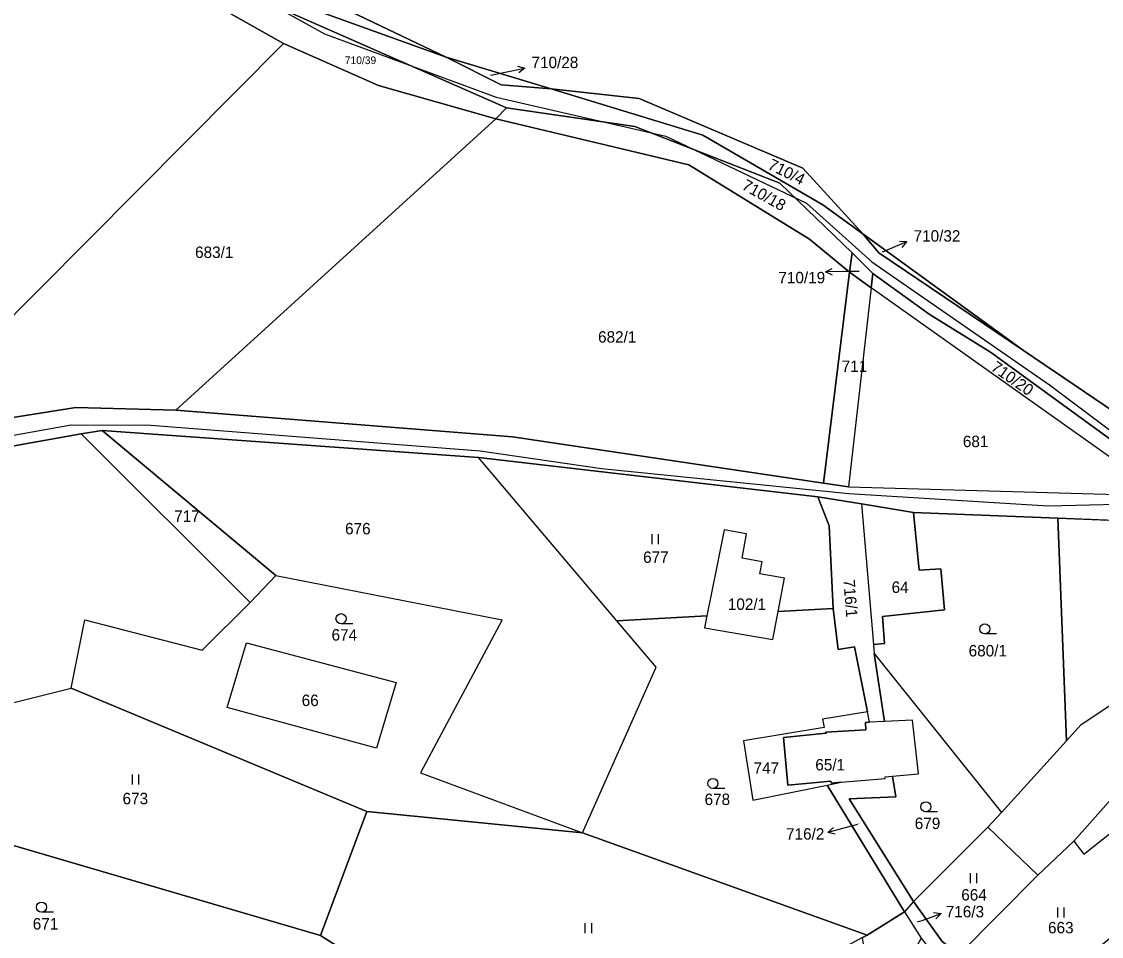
# Model space of a CAD drawing. Extents: x -590606 to -587796, y -1065936 to -1062515.
# Drawn here: x -589718.9 to -589558.4, y -1064672.2 to -1064536.2 of the extents above; entities that cross this region are included whole.
import ezdxf

# ---------------------------------------------------------------- set-up
doc = ezdxf.new("R2010")
doc.units = 0
for name, color, linetype in [('Cesty', 7, 'Continuous'), ('Parcela nároku', 7, 'Continuous'), ('Parcelní číslo', 7, 'Continuous'), ('Vnější obvod_ Studené', 7, 'Continuous'), ('Vrstva 30', 7, 'Continuous'), ('Územní plán', 7, 'Continuous')]:
    doc.layers.add(name, color=color, linetype=linetype)

msp = doc.modelspace()

# ---------------------------------------------------------------- linework, layer by layer
at = {"layer": 'Cesty'}
for points in [[(-589892.17, -1064369.93), (-589875.26, -1064390.63), (-589869.59, -1064400.17), (-589860.61, -1064415.28), (-589855.62, -1064428.91), (-589851.76, -1064436.47), (-589835.09, -1064454.08), (-589818.14, -1064470.08), (-589809.98, -1064474.85), (-589789.91, -1064479.31), (-589769.84, -1064483.14), (-589746.37, -1064490.42), (-589728.15, -1064501.15), (-589708.7, -1064515.97), (-589695.75, -1064525.84), (-589673.94, -1064537.99), (-589648.4, -1064547.43), (-589623.17, -1064553.21), (-589602.26, -1064563.18), (-589592.55, -1064571.88), (-589566.17, -1064590.19), (-589543.56, -1064607.17)], [(-589312.39, -1064575.92), (-589318.72, -1064584.83), (-589335.76, -1064596.6), (-589354.95, -1064613.9), (-589370.21, -1064620.11), (-589392.14, -1064624.65), (-589405.6, -1064625.31), (-589467.35, -1064625.2), (-589485.5, -1064624.04), (-589517.23, -1064616.87), (-589543.56, -1064607.17), (-589549.94, -1064607.84), (-589566.34, -1064608.24), (-589595.98, -1064606.38), (-589632.73, -1064602.69), (-589650.77, -1064600.08), (-589699.72, -1064596.26), (-589711.59, -1064596.2), (-589764.62, -1064605.69), (-589799.36, -1064611.91)]]:
    msp.add_lwpolyline(points, dxfattribs=at)
at = {"layer": 'Parcela nároku'}
for points in [[(-589805.3, -1064473.64), (-589768.97, -1064479.77), (-589741.12, -1064488.48), (-589688.24, -1064525.96), (-589655.82, -1064541.47), (-589681.45, -1064532.18), (-589702.19, -1064520.36), (-589727.96, -1064499.92), (-589745.58, -1064489.29), (-589769.07, -1064481.35), (-589801.78, -1064475.28)], [(-589724.71, -1064505.14), (-589693.05, -1064528.65), (-589646.88, -1064549.01), (-589648.45, -1064550.62), (-589665.91, -1064545.7), (-589680.03, -1064539.44), (-589706.11, -1064524.65), (-589725.8, -1064508.32)], [(-589725.8, -1064508.32), (-589706.11, -1064524.65), (-589680.03, -1064539.44), (-589738.08, -1064597.9), (-589752.19, -1064600.19), (-589746.83, -1064575.48), (-589738.54, -1064544.17)], [(-589680.03, -1064539.44), (-589738.08, -1064597.9), (-589710.88, -1064593.56), (-589696.02, -1064593.97), (-589648.45, -1064550.62), (-589665.91, -1064545.7)], [(-589655.82, -1064541.47), (-589640.22, -1064546.2), (-589647.67, -1064545.57)], [(-589602.81, -1064558), (-589593.92, -1064567.75), (-589599.87, -1064563.44), (-589617.67, -1064553.05), (-589640.22, -1064546.2), (-589627.14, -1064547.63)], [(-589627.8, -1064551.78), (-589606.26, -1064560.21), (-589595.48, -1064570.57), (-589595.88, -1064573.42), (-589601.81, -1064568.51), (-589619.77, -1064557.49), (-589648.45, -1064550.62), (-589646.88, -1064549.01)], [(-589619.77, -1064557.49), (-589648.45, -1064550.62), (-589696.02, -1064593.97), (-589645.99, -1064597.91), (-589599.74, -1064604.8), (-589595.88, -1064573.42), (-589601.81, -1064568.51)], [(-589593.92, -1064567.75), (-589570.02, -1064585.07), (-589591.52, -1064570.55)], [(-589595.48, -1064570.57), (-589592.41, -1064573.65), (-589592.68, -1064575.78), (-589595.88, -1064573.42)], [(-589599.74, -1064604.8), (-589595.88, -1064573.42), (-589592.68, -1064575.78), (-589596.03, -1064605.35)], [(-589592.41, -1064573.65), (-589584.07, -1064579.7), (-589574.93, -1064585.33), (-589545.68, -1064606.61), (-589549.09, -1064606.72), (-589592.68, -1064575.78)], [(-589592.68, -1064575.78), (-589596.03, -1064605.35), (-589549.09, -1064606.72)], [(-589755.28, -1064641.85), (-589755.52, -1064646.24), (-589711.55, -1064635.28), (-589709.54, -1064625.13), (-589692.09, -1064629.64), (-589684.98, -1064622.56), (-589710.09, -1064597.48), (-589753, -1064605.14)], [(-589681.13, -1064618.54), (-589706.94, -1064597.01), (-589710.09, -1064597.48), (-589684.98, -1064622.56)], [(-589630.46, -1064625.3), (-589651.05, -1064601), (-589706.94, -1064597.01), (-589681.13, -1064618.54), (-589647.53, -1064625.14), (-589659.66, -1064647.91), (-589635.57, -1064656.82), (-589624.62, -1064632.2)], [(-589651.05, -1064601), (-589600.62, -1064606.83), (-589598.89, -1064611.14), (-589598.31, -1064623.43), (-589606.49, -1064623.91), (-589605.57, -1064618.96), (-589609.22, -1064618.29), (-589608.89, -1064616.51), (-589611.85, -1064615.97), (-589611.19, -1064612.37), (-589614.53, -1064611.74), (-589615.62, -1064617.2), (-589617.08, -1064624.52), (-589630.46, -1064625.3)], [(-589594.13, -1064607.9), (-589592.33, -1064628.79), (-589592.21, -1064630.16), (-589590.7, -1064640.26), (-589592.9, -1064640.37), (-589593.2, -1064638.84), (-589595.13, -1064629.17), (-589597.57, -1064629.54), (-589598.31, -1064623.43), (-589598.89, -1064611.14), (-589600.62, -1064606.83)], [(-589590.7, -1064628.65), (-589591, -1064624.64), (-589581.76, -1064623.64), (-589582.33, -1064617.54), (-589585.54, -1064617.76), (-589586.36, -1064609.18), (-589594.13, -1064607.9), (-589592.33, -1064628.79)], [(-589564.95, -1064610.02), (-589586.36, -1064609.18), (-589585.54, -1064617.76), (-589582.33, -1064617.54), (-589581.76, -1064623.64), (-589591, -1064624.64), (-589590.7, -1064628.65), (-589592.33, -1064628.79), (-589592.21, -1064630.16), (-589573.32, -1064653.79), (-589563.64, -1064643.14)], [(-589542.13, -1064612.29), (-589546.05, -1064609.19), (-589552.79, -1064610.5), (-589564.95, -1064610.02), (-589563.64, -1064643.14), (-589561.44, -1064640.72), (-589546.87, -1064631.05), (-589529.07, -1064623.08), (-589516.66, -1064621.08)], [(-589608.89, -1064616.51), (-589611.85, -1064615.97), (-589611.19, -1064612.37), (-589614.53, -1064611.74), (-589615.62, -1064617.2), (-589617.08, -1064624.52), (-589617.45, -1064626.35), (-589607.26, -1064628.07), (-589606.49, -1064623.91), (-589605.57, -1064618.96), (-589609.22, -1064618.29)], [(-589709.54, -1064625.13), (-589692.09, -1064629.64), (-589684.98, -1064622.56), (-589681.13, -1064618.54), (-589647.53, -1064625.14), (-589659.66, -1064647.91), (-589635.57, -1064656.82), (-589667.65, -1064653.64), (-589711.55, -1064635.28)], [(-589575.32, -1064655.99), (-589573.32, -1064653.79), (-589563.64, -1064643.14), (-589561.44, -1064640.72), (-589546.87, -1064631.05), (-589529.07, -1064623.08), (-589516.66, -1064621.08), (-589504.98, -1064623.35), (-589504.71, -1064638.79), (-589523.85, -1064638.97), (-589544.78, -1064642.49), (-589555.43, -1064650), (-589562.54, -1064658.03), (-589567.91, -1064663.13)], [(-589635.57, -1064656.82), (-589624.62, -1064632.2), (-589630.46, -1064625.3), (-589617.08, -1064624.52), (-589617.45, -1064626.35), (-589607.26, -1064628.07), (-589606.49, -1064623.91), (-589598.31, -1064623.43), (-589597.57, -1064629.54), (-589595.13, -1064629.17), (-589593.2, -1064638.84), (-589599.89, -1064639.89), (-589599.66, -1064641.16), (-589611.63, -1064643.12), (-589610.28, -1064651.95), (-589599.22, -1064649.72), (-589587.72, -1064668.56), (-589593.25, -1064672.02)], [(-589688.38, -1064638.18), (-589685.52, -1064628.58), (-589663.27, -1064634.48), (-589666.2, -1064644.2)], [(-589663.27, -1064634.48), (-589666.2, -1064644.2), (-589688.38, -1064638.18), (-589685.52, -1064628.58)], [(-589592.21, -1064630.16), (-589573.32, -1064653.79), (-589575.32, -1064655.99), (-589586.37, -1064667), (-589595.93, -1064651.74), (-589589.02, -1064651.45), (-589589.48, -1064648.38), (-589585.62, -1064648.04), (-589586.55, -1064640.05), (-589590.7, -1064640.26)], [(-589711.55, -1064635.28), (-589667.65, -1064653.64), (-589674.51, -1064672.1), (-589730.86, -1064655.58), (-589753.92, -1064654.08), (-589755.52, -1064646.24)], [(-589593.2, -1064638.84), (-589599.89, -1064639.89), (-589599.66, -1064641.16), (-589611.63, -1064643.12), (-589610.28, -1064651.95), (-589599.22, -1064649.72), (-589597.13, -1064649.3), (-589598.62, -1064649.43), (-589598.65, -1064649.13), (-589605.07, -1064649.72), (-589605.69, -1064642.65), (-589599.38, -1064641.99), (-589599.39, -1064641.86), (-589593.48, -1064641.5), (-589593.53, -1064640.4), (-589592.9, -1064640.37)], [(-589503.84, -1064654.9), (-589504.71, -1064638.79), (-589523.85, -1064638.97), (-589544.78, -1064642.49), (-589555.43, -1064650), (-589562.54, -1064658.03), (-589561.08, -1064660), (-589553.65, -1064654.07), (-589548.24, -1064668.99), (-589539.78, -1064668.95)], [(-589593.48, -1064641.5), (-589599.39, -1064641.86), (-589599.38, -1064641.99), (-589605.69, -1064642.65), (-589605.07, -1064649.72), (-589598.65, -1064649.13), (-589598.62, -1064649.43), (-589597.13, -1064649.3), (-589590.58, -1064648.73), (-589590.6, -1064648.48), (-589589.48, -1064648.38), (-589585.62, -1064648.04), (-589586.55, -1064640.05), (-589590.7, -1064640.26), (-589592.9, -1064640.37), (-589593.53, -1064640.4)], [(-589599.22, -1064649.72), (-589597.13, -1064649.3), (-589590.58, -1064648.73), (-589590.6, -1064648.48), (-589589.48, -1064648.38), (-589589.02, -1064651.45), (-589595.93, -1064651.74), (-589586.37, -1064667), (-589587.72, -1064668.56)], [(-589753.3, -1064666.31), (-589751.87, -1064684.47), (-589758.89, -1064685.17), (-589755.37, -1064668.5), (-589765.53, -1064670.88), (-589769.01, -1064656.08), (-589753.92, -1064654.08), (-589730.86, -1064655.58), (-589674.51, -1064672.1), (-589658.93, -1064681.99), (-589653.5, -1064688.41), (-589638.89, -1064692.66), (-589640.04, -1064694.73), (-589662.7, -1064687.77), (-589676.27, -1064682.49), (-589698.92, -1064680.19), (-589732.55, -1064682.34), (-589733.53, -1064672.91), (-589741.81, -1064673.48), (-589742.61, -1064665.31)], [(-589667.65, -1064653.64), (-589635.57, -1064656.82), (-589593.25, -1064672.02), (-589593.95, -1064672.4), (-589609.9, -1064681.01), (-589638.89, -1064692.66), (-589653.5, -1064688.41), (-589658.93, -1064681.99), (-589674.51, -1064672.1)], [(-589579.59, -1064674.92), (-589567.91, -1064663.13), (-589562.54, -1064658.03), (-589561.08, -1064660), (-589553.65, -1064654.07), (-589548.24, -1064668.99), (-589556.93, -1064672.33), (-589569.41, -1064682.53)], [(-589567.91, -1064663.13), (-589575.32, -1064655.99), (-589586.37, -1064667), (-589582.11, -1064672.99), (-589579.59, -1064674.92)], [(-589569.41, -1064682.53), (-589579.59, -1064674.92), (-589582.11, -1064672.99), (-589586.37, -1064667), (-589587.72, -1064668.56), (-589585.22, -1064672.49), (-589583.34, -1064674.92), (-589567.53, -1064686.1), (-589568.49, -1064683.25)], [(-589593.25, -1064672.02), (-589587.72, -1064668.56), (-589585.22, -1064672.49), (-589589.6, -1064680.44), (-589579.69, -1064704.22), (-589564.75, -1064729.88), (-589565.29, -1064732.38), (-589572.86, -1064721.23), (-589583.32, -1064702.97), (-589592.26, -1064683.72), (-589593.95, -1064672.4)]]:
    msp.add_lwpolyline(points, close=True, dxfattribs=at)
for points in [[(-589386.23, -1064621.24), (-589413.51, -1064622.05), (-589435.93, -1064621.07), (-589457.96, -1064622.14), (-589477.4, -1064620.92), (-589498.57, -1064618.24), (-589523.41, -1064611.81), (-589544.52, -1064602.39), (-589570.02, -1064585.07), (-589593.92, -1064567.75), (-589602.81, -1064558), (-589627.14, -1064547.63), (-589640.22, -1064546.2), (-589655.82, -1064541.47), (-589688.24, -1064525.96)], [(-589681.45, -1064532.18), (-589655.82, -1064541.47), (-589647.67, -1064545.57), (-589640.22, -1064546.2), (-589617.67, -1064553.05), (-589599.87, -1064563.44), (-589593.92, -1064567.75), (-589591.52, -1064570.55), (-589570.02, -1064585.07), (-589544.52, -1064602.39), (-589541.19, -1064604.66), (-589542.09, -1064606.65), (-589543.01, -1064608.6), (-589545.68, -1064606.61), (-589574.93, -1064585.33), (-589584.07, -1064579.7), (-589592.41, -1064573.65), (-589595.48, -1064570.57), (-589606.26, -1064560.21), (-589627.8, -1064551.78), (-589646.88, -1064549.01), (-589693.05, -1064528.65)], [(-589850.56, -1064625.55), (-589808.34, -1064612.83), (-589752.19, -1064600.19), (-589738.08, -1064597.9), (-589710.88, -1064593.56), (-589696.02, -1064593.97), (-589645.99, -1064597.91), (-589599.74, -1064604.8), (-589596.03, -1064605.35), (-589549.09, -1064606.72), (-589546.05, -1064609.19), (-589552.79, -1064610.5), (-589564.95, -1064610.02), (-589586.36, -1064609.18), (-589594.13, -1064607.9), (-589600.62, -1064606.83), (-589651.05, -1064601), (-589706.94, -1064597.01), (-589710.09, -1064597.48), (-589753, -1064605.14), (-589810.83, -1064617.52), (-589850.49, -1064629.2)]]:
    msp.add_lwpolyline(points, dxfattribs=at)
at = {"layer": 'Parcelní číslo'}
for p, q in [((-589647.09, -1064543.71), (-589644.15, -1064543.1)), ((-589649.19, -1064544.14), (-589647.09, -1064543.71)), ((-589590.13, -1064570.06), (-589587.36, -1064568.9)), ((-589590.95, -1064570.4), (-589590.13, -1064570.06)), ((-589596.44, -1064573.36), (-589599.44, -1064573.4)), ((-589594.46, -1064573.34), (-589596.44, -1064573.36)), ((-589594.71, -1064655.57), (-589596.21, -1064655.98)), ((-589596.21, -1064655.98), (-589599.1, -1064656.77)), ((-589585.76, -1064670.07), (-589585.1, -1064669.83)), ((-589585.1, -1064669.83), (-589582.29, -1064668.79))]:
    msp.add_line(p, q, dxfattribs=at)
for points in [[(-589645.23, -1064542.82), (-589644.15, -1064543.1), (-589645.03, -1064543.8)], [(-589588.48, -1064568.83), (-589587.36, -1064568.9), (-589588.09, -1064569.75)], [(-589598.43, -1064573.88), (-589599.44, -1064573.4), (-589598.45, -1064572.88)], [(-589598.01, -1064656.99), (-589599.1, -1064656.77), (-589598.27, -1064656.03)], [(-589583.4, -1064668.67), (-589582.29, -1064668.79), (-589583.05, -1064669.61)]]:
    msp.add_lwpolyline(points, dxfattribs=at)
at = {"layer": 'Vnější obvod_ Studené'}
for p, q in [((-589655.82, -1064541.47), (-589688.24, -1064525.96)), ((-589640.22, -1064546.2), (-589655.82, -1064541.47)), ((-589627.14, -1064547.63), (-589640.22, -1064546.2)), ((-589602.81, -1064558), (-589627.14, -1064547.63)), ((-589593.92, -1064567.75), (-589602.81, -1064558)), ((-589570.02, -1064585.07), (-589593.92, -1064567.75)), ((-589544.52, -1064602.39), (-589570.02, -1064585.07)), ((-589753, -1064605.14), (-589710.09, -1064597.48)), ((-589710.09, -1064597.48), (-589706.94, -1064597.01)), ((-589706.94, -1064597.01), (-589651.05, -1064601)), ((-589651.05, -1064601), (-589600.62, -1064606.83)), ((-589600.62, -1064606.83), (-589594.13, -1064607.9)), ((-589594.13, -1064607.9), (-589586.36, -1064609.18)), ((-589586.36, -1064609.18), (-589564.95, -1064610.02)), ((-589564.95, -1064610.02), (-589552.79, -1064610.5))]:
    msp.add_line(p, q, dxfattribs=at)
at = {"layer": 'Vrstva 30'}
for p, q in [((-589625.28, -1064612.41), (-589625.28, -1064613.91)), ((-589624.26, -1064613.91), (-589624.26, -1064612.41)), ((-589669.71, -1064625.72), (-589671.46, -1064625.72)), ((-589574.03, -1064627.24), (-589575.78, -1064627.24)), ((-589702.52, -1064648.15), (-589702.52, -1064649.65)), ((-589701.49, -1064649.65), (-589701.49, -1064648.15)), ((-589614.44, -1064650.21), (-589616.19, -1064650.21)), ((-589582.8, -1064653.68), (-589584.55, -1064653.68)), ((-589577.98, -1064662.79), (-589577.98, -1064664.29)), ((-589576.95, -1064664.29), (-589576.95, -1064662.79)), ((-589714.22, -1064668.62), (-589715.97, -1064668.62)), ((-589564.99, -1064667.92), (-589564.99, -1064669.42)), ((-589563.96, -1064669.42), (-589563.96, -1064667.92)), ((-589635.24, -1064670.24), (-589635.24, -1064671.74)), ((-589634.21, -1064671.74), (-589634.21, -1064670.24))]:
    msp.add_line(p, q, dxfattribs=at)
for centre in [(-589671.46, -1064624.97), (-589575.78, -1064626.49), (-589616.19, -1064649.46), (-589584.55, -1064652.93), (-589715.97, -1064667.87)]:
    msp.add_circle(centre, 0.75, dxfattribs=at)
at = {"layer": 'Územní plán'}
msp.add_lwpolyline([(-589808.25, -1064610.3), (-589813.71, -1064476.97), (-589803.68, -1064480.89), (-589763.64, -1064487.8), (-589734.97, -1064501.33), (-589725.8, -1064508.32), (-589706.11, -1064524.65), (-589680.03, -1064539.44), (-589665.91, -1064545.7), (-589648.45, -1064550.62), (-589634.11, -1064554.06), (-589619.77, -1064557.49), (-589601.81, -1064568.51), (-589595.88, -1064573.42), (-589599.74, -1064604.8), (-589645.99, -1064597.91), (-589696.02, -1064593.97), (-589710.88, -1064593.56), (-589738.08, -1064597.9), (-589752.19, -1064600.19), (-589789.05, -1064603.26), (-589808.25, -1064610.3)], dxfattribs=at)

# ---------------------------------------------------------------- texts
at = {"layer": 'Parcela nároku'}
for s, height, p in [('710/39', 1.14, (-589670.9, -1064542.5)), ('710/28', 0.1, (-589649.39, -1064544.14)), ('683/1', 1.7, (-589693.15, -1064571.33)), ('710/32', 0.1, (-589591.15, -1064570.4)), ('710/19', 0.1, (-589594.64, -1064573.34)), ('682/1', 1.7, (-589633.26, -1064583.92)), ('711', 1.7, (-589597.05, -1064588.29)), ('681', 1.7, (-589579.04, -1064599.46)), ('717', 1.7, (-589696.26, -1064610.57)), ('676', 1.7, (-589670.86, -1064612.43)), ('677', 1.7, (-589626.56, -1064616.67)), ('64', 1.7, (-589589.63, -1064621.14)), ('102/1', 1.7, (-589613.97, -1064623.66)), ('674', 1.7, (-589672.87, -1064628.23)), ('680/1', 1.7, (-589578.18, -1064630.58)), ('66', 1.7, (-589677.31, -1064637.96)), ('65/1', 1.7, (-589600.97, -1064647.53)), ('747', 1.7, (-589610.14, -1064648.02)), ('673', 1.7, (-589703.93, -1064652.56)), ('678', 1.7, (-589617.43, -1064652.68)), ('716/2', 0.1, (-589594.71, -1064655.57)), ('679', 1.7, (-589586.19, -1064656.25)), ('664', 1.7, (-589579.28, -1064666.88)), ('671', 1.7, (-589717.28, -1064671.19)), ('716/3', 0.1, (-589585.76, -1064670.07)), ('663', 1.7, (-589566.38, -1064671.76))]:
    msp.add_text(s, height=height, dxfattribs=at).set_placement(p)
for s, rotation, p in [('710/4', 333.435, (-589608.16, -1064558.01)), ('710/18', 330.7379, (-589612.03, -1064561.02)), ('710/20', 325.0279, (-589575.01, -1064587.93)), ('716/1', 274.5, (-589596.81, -1064619.17))]:
    msp.add_text(s, height=1.7, rotation=rotation, dxfattribs=at).set_placement(p)
at = {"layer": 'Parcelní číslo'}
for s, p in [('710/28', (-589643.15, -1064543.1)), ('710/32', (-589586.36, -1064568.9)), ('710/19', (-589606.46, -1064575.1)), ('716/2', (-589605.32, -1064657.82)), ('716/3', (-589581.58, -1064669.38))]:
    msp.add_text(s, height=1.7, dxfattribs=at).set_placement(p)

doc.saveas('drawing.dxf')
